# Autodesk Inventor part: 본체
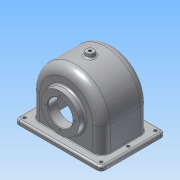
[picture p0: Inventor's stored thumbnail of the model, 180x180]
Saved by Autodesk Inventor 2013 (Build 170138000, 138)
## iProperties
Created: 2015-09
Part Number: 본체
Material: 알루미늄 6061
Document SubType Name: Modeling
Designer: Administrator
Density: 2.71 g/cm^3
Mass: 724.641 g
Surface Area: 889.989 cm^2
Volume: 267.395 cm^3
Author: Administrator
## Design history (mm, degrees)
sketch "스케치1"
  geometry: L1 (-57, 57)-(57, 57); L2 (57, 57)-(57, -47); L3 (57, -47)-(-57, -47); L4 (-57, -47)-(-57, 57); 2 further points
  constraints: 8 end point, 2 parallel, 1 horizontal, 1 midpoint, 1 perpendicular, 1 vertical alignment
  dimensions: "d0" = 47 distance from line of L3 point (0, 0); "d1" = 104 distance of L1.end L2.end; "d2" = 114 distance of L2.end L3.end
extrude "돌출1" new body sketch "스케치1" stored distance "d3" = 77; taper "d4" = 0 deg
node "작업 평면1"
sketch "스케치2"
  geometry: L1 (-70, 52)-(70, 52); L2 (70, 52)-(70, -52); L3 (70, -52)-(-70, -52); L4 (-70, -52)-(-70, 52); L5 (51, 33.5)-(-51, 33.5); L6 (-51, 33.5)-(-51, -33.5); L7 (-51, -33.5)-(51, -33.5); L8 (51, -33.5)-(51, 33.5); 5 further points
  constraints: 16 end point, 4 midpoint, 4 parallel, 2 horizontal, 2 horizontal alignment, 2 perpendicular, 2 vertical alignment
  dimensions: "d6" = 140 distance of L2.end L3.end; "d8" = 104 distance of L3.end L1.start; "d9" = 102 distance of L5.start L5.end; "d10" = 67 distance of L7.end L5.start
extrude "돌출2" join sketch "스케치2" distance "d11" = 7; taper "d12" = 0 deg
extrude "돌출3" cut sketch "스케치2" distance "d13" = 98; taper "d14" = 0 deg
fillet "모깎기1" dims "d15" = 57, "d16" = 51
sketch "스케치8"
  geometry: C1 r 31 at (0, 0); A1 r 57 centre (0, 0) between (57, 0) and (-57, 0) reference
  constraints: 1 centre point, 1 coincident
  dimensions: "d57" = 62 diameter of C1
extrude "돌출7" join sketch "스케치8" distance "d59" = 10; taper "d60" = 0 deg
node "작업 평면4"
sketch "스케치6"
  geometry: C1 r 28 at (0, 0); 1 further point
  constraints: 1 centre point, 1 coincident
  dimensions: "d31" = 56 diameter of C1
extrude "돌출6" join sketch "스케치6" stored distance "d33" = 98; taper "d34" = 40 deg
sketch "스케치7"
  geometry: L1 (38.5, 57)-(38.5, 0) reference; L2 (19.5, 28)-(33.5, 39.747) reference; L3 (19.5, 28)-(19.5, -28) reference; L4 (38.5, 0)-(38.5, 37.416); L5 (38.5, 37.416)-(33.237, 33); L6 (33.237, 33)-(35.5, 33); L7 (35.5, 33)-(35.5, 0); L8 (35.5, 0)-(38.5, 0); 1 further point
  constraints: 10 end point, 3 perpendicular, 1 parallel, 1 point on line
  dimensions: "d35" = 16 distance between parallel lines of L7 L3; "d36" = 5 distance between parallel lines of L5 L2; "d37" = 33 distance between parallel lines of L8 L6
revolve "회전1" sketch "스케치7" stored, may be unused: angle "d38" = 90 deg
hole "구멍1" diameter "d41" = 40; stored, may be unused: countersink angle "d45" = 90 deg, drill point angle "d47" = 0 deg; dims "d39" = 10, "d40" = 10, "d42" = 6, "d43" = 4, "d44" = 2, "d46" = 17
hole "구멍3" diameter "d63" = 40; stored, may be unused: countersink angle "d67" = 90 deg, drill point angle "d69" = 0 deg; dims "d61" = 10, "d62" = 10, "d64" = 6, "d65" = 4, "d66" = 2, "d68" = 17
sketch "스케치9"
  geometry: C1 r 20 at (0, 0) reference; 1 further point
  constraints: 1 vertical alignment
  dimensions: "d70" = 28 distance of point (0, -28) C1.centre
hole "구멍4" sketch "스케치9" at (0, -28) diameter "d71" = 2.459; stored, may be unused: countersink angle "d75" = 90 deg, drill point angle "d77" = 118 deg; dims "d72" = 7, "d73" = 4, "d74" = 2, "d76" = 9
sketch "스케치10"
  geometry: C1 r 20 at (0, 0) reference; 1 further point
  constraints: 1 vertical alignment
  dimensions: "d81" = 24 distance of point (0, 24) C1.centre
hole "구멍5" sketch "스케치10" at (0, 24) diameter "d82" = 2.459; stored, may be unused: countersink angle "d86" = 90 deg, drill point angle "d88" = 118 deg; dims "d83" = 6, "d84" = 4, "d85" = 2, "d87" = 8
node "작업 평면5"
sketch "스케치11"
  geometry: C1 r 6 at (0, 0); 1 further point
  constraints: 1 centre point, 1 coincident
  dimensions: "d93" = 12 diameter of C1
extrude "돌출8" join sketch "스케치11" stored distance "d95" = 10; taper "d96" = 10 deg
hole "구멍6" diameter "d99" = 4.459; stored, may be unused: countersink angle "d103" = 90 deg, drill point angle "d105" = 118 deg; dims "d97" = 10, "d98" = 10, "d100" = 20, "d101" = 4, "d102" = 2, "d104" = 8
sketch "스케치12"
  geometry: 4 further points
  constraints: 2 vertical alignment
  dimensions: "d106" = 62 distance of point (0, 0) point (-62, 0); "d107" = 44 distance of point (-62, 44) point (-62, 0); "d108" = 44 distance of point (-62, -44) point (-62, 0)
hole "구멍7" sketch "스케치12" at (-62, 44), (-62, 0), (-62, -44) diameter "d109" = 5; stored, may be unused: countersink angle "d113" = 90 deg, drill point angle "d115" = 0 deg; dims "d110" = 20, "d111" = 4, "d112" = 2, "d114" = 8
fillet "모깎기2" dims "d116" = 14, "d117" = 9, "d118" = 7, "d119" = 3
fillet "모깎기3" dims "d120" = 1
chamfer "모따기1" distance "d121" = 1; stored, may be unused: second distance "d122" = 2, angle "d123" = 45 deg
sketch "스케치13"
  geometry: L1 (0, 49)-(0, 0) reference; L2 (-47, 49)-(-47, 0) reference; 3 further points
  constraints: 1 horizontal alignment, 1 midpoint, 1 other
  dimensions: "d124" = 30 distance from line of L2 point (-17, 24.5)
feature "엠보싱1" sketch "스케치13" dims "d0" = 47, "d1" = 104, "d2" = 114, "d13" = 98, "d125" = 0.5, "d126" = 0
node "솔리드1"
pattern_circular "원형 패턴1" dims angle "d79" = 360 deg
pattern_circular "원형 패턴2" dims angle "d90" = 360 deg
mirror "대칭1"
other parameters: "d5" = -47, "d30" = -19, "d92" = 63
